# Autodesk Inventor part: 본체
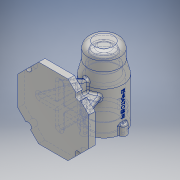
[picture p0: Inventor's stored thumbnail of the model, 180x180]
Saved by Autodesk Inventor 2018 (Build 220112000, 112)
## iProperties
Created: 2019-12
Part Number: 본체
Material: 알루미늄 6061
Document SubType Name: Modeling
Designer: Administrator
Density: 2.7 g/cm^3
Appearance: 알루미늄 - 평지
Mass: 726.082 g
Surface Area: 714.194 cm^2
Volume: 268.919 cm^3
Author: Administrator
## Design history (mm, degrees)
sketch "스케치1"
  geometry: L1 (56.037, -23.106)-(23.286, -55.963); L2 (23.286, -55.963)-(-23.106, -56.037); L3 (-23.106, -56.037)-(-55.963, -23.286); L4 (-55.963, -23.286)-(-56.037, 23.106); L5 (-56.037, 23.106)-(-23.286, 55.963); L6 (-23.286, 55.963)-(23.106, 56.037); L7 (23.106, 56.037)-(55.963, 23.286); L8 (55.963, 23.286)-(56.037, -23.106); 1 further point
  constraints: 16 end point
  dimensions: "d0" = 112 distance between parallel lines of L6 L2
extrude "돌출1" new body sketch "스케치1" distance "d1" = 10; taper "d2" = 0 deg
sketch "스케치2"
  geometry: L1 (0, -23.286)-(0, 23.106) reference; L2 (80, -55.359)-(110, -55.359); L3 (110, -55.359)-(110, 11.641); L4 (105, 31.641)-(105, 56.641); L5 (105, 56.641)-(80, 56.641); L6 (80, -55.359)-(80, 56.641); L7 (110, 11.641)-(105, 31.641); 1 further point
  constraints: 12 end point, 1 horizontal, 1 perpendicular, 1 vertical
  dimensions: "d4" = 112 distance between parallel lines of L5 L2; "d6" = 80 distance between parallel lines of L1 L6; "d7" = 50 diameter of L4 L6; "d9" = 60 diameter of L3 L6; "d10" = 67 distance of L2.end L3.end; "d11" = 25 distance of L4.start L4.end
revolve "회전1" sketch "스케치2" stored, may be unused: angle "d12" = 90 deg
fillet "모깎기1" dims "d13" = 10
sketch "스케치4"
  geometry: L1 (53.214, -30.963)-(53.214, 17.886); L2 (53.214, 17.886)-(10, 38.037); L3 (10, -30.963)-(53.214, -30.963); L4 (0, -55.963)-(10, -55.963) reference; L5 (0, 56.037)-(10, 56.037) reference; L6 (10, 38.037)-(10, -30.963); L7 (10, 23.286)-(10, 56.037) reference
  constraints: 8 end point, 1 collinear
  dimensions: "d32" = 25 distance between parallel lines of L3 L4; "d33" = 18 distance from line of L5 L2.end; "d92" = 115 deg angle of L7 L2
extrude "돌출2" join sketch "스케치4" stored distance "d34" = 8; taper "d35" = 0 deg
sketch "스케치5"
  geometry: L1 (18.528, 58.105)-(-18.454, 58.105); L2 (-18.454, 58.105)-(-35.963, 10); L3 (36.037, 10)-(18.528, 58.105); L4 (-55.963, 0)-(-55.963, 10) reference; L5 (56.037, 0)-(56.037, 10) reference; L6 (36.037, 10)-(-35.963, 10); 1 further point
  constraints: 8 end point, 2 horizontal
  dimensions: "d38" = 20 distance from line of L2.end L4; "d39" = 20 distance from line of L5 L3.start
extrude "돌출3" join sketch "스케치5" stored distance "d40" = 8; taper "d41" = 0 deg
sketch "스케치6"
  geometry: L1 (-23.106, -56.037)-(-55.963, -23.286) reference; L2 (56.037, -23.106)-(23.286, -55.963) reference; L3 (23.106, 56.037)-(55.963, 23.286) reference; L4 (-56.037, 23.106)-(-23.286, 55.963) reference; C1 r 5 at (-39.534, -39.662); C2 r 5 at (39.662, -39.534); C3 r 5 at (39.534, 39.662); C4 r 5 at (-39.662, 39.534); 1 further point
  constraints: 4 centre point, 4 midpoint
  dimensions: "d43" = 10 diameter of C1; "d44" = 10 diameter of C2; "d45" = 10 diameter of C3; "d46" = 10 diameter of C4
extrude "돌출4" cut sketch "스케치6" extent not by distance; stored distance "d51" = 8; taper "d52" = 0 deg
sketch "스케치7"
  geometry: L1 (50, -55.359)-(110, -55.359) reference; L2 (80, -55.359)-(101, -55.359); L3 (101, -55.359)-(101, -40.359); L4 (101, -40.359)-(80, -40.359); L5 (80, -40.359)-(80, -55.359); L6 (80, -40.359)-(104, -40.359); L7 (104, -40.359)-(104, 13.641); L8 (104, 13.641)-(80, 13.641); L9 (80, 13.641)-(80, -40.359); L10 (80, 13.641)-(101, 13.641); L11 (101, 13.641)-(101, 25.641); L12 (101, 25.641)-(80, 25.641); L13 (80, 25.641)-(80, 13.641); L14 (80, 25.641)-(97.5, 25.641); L15 (97.5, 25.641)-(97.5, 43.641); L16 (97.5, 43.641)-(80, 43.641); L17 (80, 43.641)-(80, 25.641); L18 (80, 43.641)-(96, 43.641); L19 (96, 43.641)-(96, 47.641); L20 (96, 47.641)-(80, 47.641); L21 (80, 47.641)-(80, 43.641); L22 (80, 47.641)-(90.5, 47.641); L23 (90.5, 47.641)-(90.5, 50.641); L24 (90.5, 50.641)-(80, 50.641); L25 (80, 50.641)-(80, 47.641); 1 further point
  constraints: 48 end point, 12 parallel, 6 horizontal, 6 perpendicular, 1 midpoint
  dimensions: "d53" = 15 distance between parallel lines of L4 L2; "d54" = 42 diameter of L3 L5; "d55" = 48 diameter of L7 L9; "d56" = 42 diameter of L11 L13; "d57" = 54 distance of L6.end L7.end; "d58" = 12 distance of L10.end L11.end; "d59" = 18 distance of L14.end L15.end; "d60" = 35 diameter of L15 L17; "d61" = 4 distance of L18.end L19.end; "d62" = 32 diameter of L19 L21; "d63" = 21 diameter of L23 L25; "d64" = 3 distance of L22.end L23.end
revolve "회전2" sketch "스케치7" stored, may be unused: angle "d65" = 90 deg
fillet "모깎기2" dims "d66" = 3
chamfer "모따기1" distance "d67" = 1; stored, may be unused: second distance "d68" = 2, angle "d69" = 45 deg
sketch "스케치8"
  geometry: C1 r 6 at (0, 30); C2 r 6 at (30, 0); C3 r 6 at (-30, 0); C4 r 6 at (0, -30); A1 r 30 centre (0, 0) between (0, 30) and (30, 0) reference; 1 further point
  constraints: 4 centre point, 2 point on circle
  dimensions: "d70" = 12 diameter of C1; "d71" = 12 diameter of C2
extrude "돌출5" join sketch "스케치8" distance "d72" = 16; taper "d73" = 0 deg
sketch "스케치9"
  geometry: A1 r 6 centre (-30, -30) between (-29.4, -24.03) and (-29.4, -35.97) reference; A2 r 6 centre (0, 0) between (5.97, -0.6) and (-5.97, -0.6) reference; A3 r 6 centre (30, -30) between (29.4, -35.97) and (29.4, -24.03) reference; A4 r 6 centre (0, -60) between (-5.97, -59.4) and (5.97, -59.4) reference; 5 further points
  constraints: 4 coincident
hole "구멍1" sketch "스케치9" at (-30, -30), (0, 0), (30, -30), (0, -60) diameter "d74" = 3.242; stored, may be unused: countersink angle "d78" = 90 deg, drill point angle "d80" = 118 deg; dims "d75" = 8, "d76" = 4, "d77" = 2, "d79" = 11
fillet "모깎기3" dims "d81" = 3
fillet "모깎기4" dims "d82" = 3
fillet "모깎기5" dims "d83" = 3
fillet "모깎기6" dims "d84" = 3
fillet "모깎기7" dims "d85" = 3
fillet "모깎기8" dims "d86" = 0.3
node "작업 평면1"
sketch "스케치10"
  geometry: L1 (8.017, -33.5)-(28.909, -33.5) reference; L2 (-15, 78.5)-(15, 78.5) reference; 2 further points
  constraints: 1 other
  dimensions: "d87" = 41 distance from line of L1 point (0, 7.5)
feature "엠보싱1" sketch "스케치10" dims "d0" = 112, "d13" = 10, "d88" = 0.5, "d89" = 0
fillet "모깎기9" dims "d90" = 1
fillet "모깎기10" dims "d91" = 3
node "솔리드1"
other parameters: "d22" = 4, "d23" = 4
